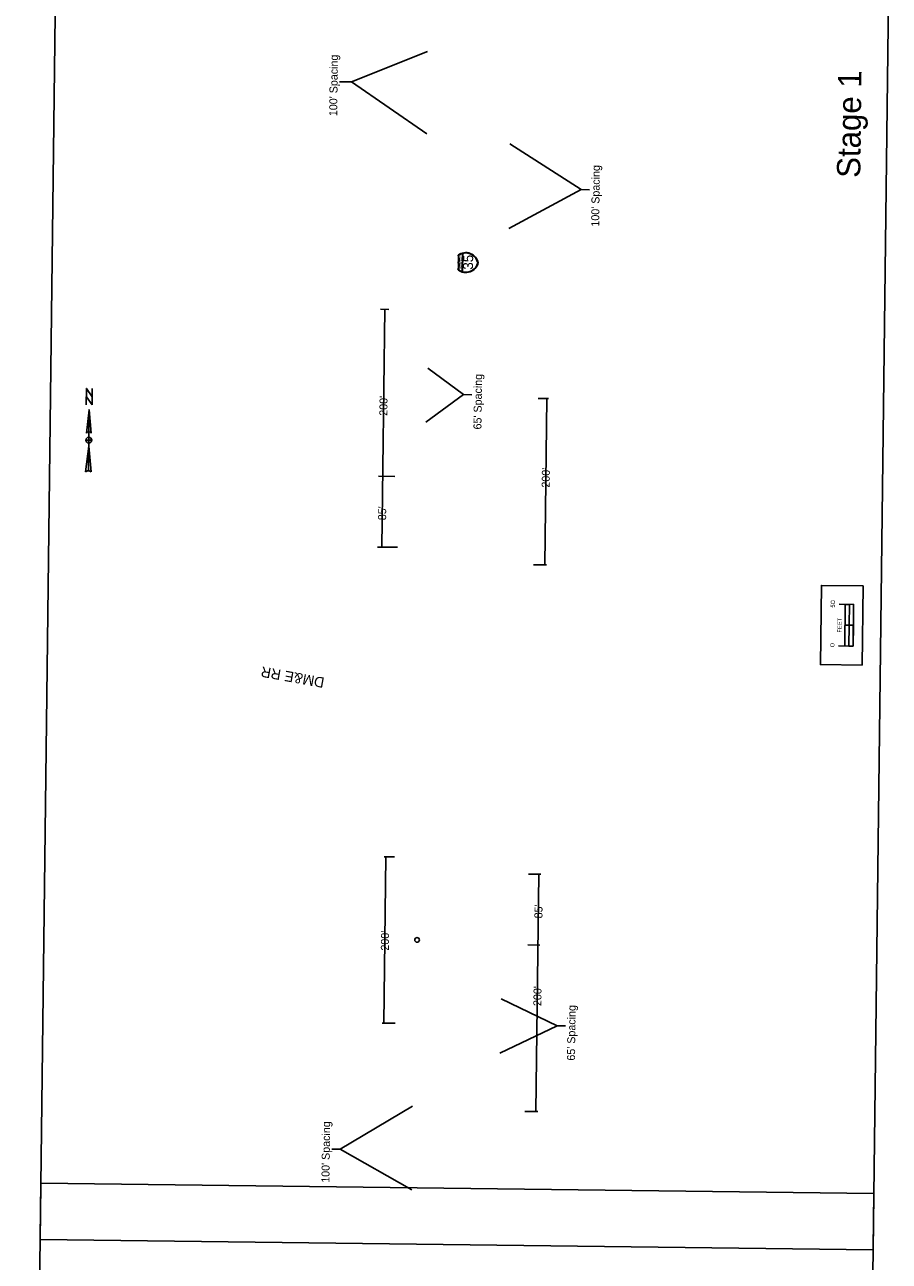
# Model space of a CAD drawing. Extents: x 4959127 to 4960275, y 3872379 to 3884458.
# Drawn here: x 4959182 to 4960220, y 3878365 to 3879849 of the extents above; entities that cross this region are included whole.
import ezdxf

# ---------------------------------------------------------------- set-up
doc = ezdxf.new("R2010")
doc.units = 0
for name, color, linetype in [('Cell', 7, 'Continuous'), ('dsnCellElements', 7, 'Continuous'), ('dsnCellsHighwaySymbols', 7, 'Continuous'), ('dsnCellsScaleBlock', 7, 'Continuous'), ('NamedBoundary', 7, 'Continuous'), ('SheetText', 7, 'Continuous'), ('Text', 7, 'Continuous')]:
    doc.layers.add(name, color=color, linetype=linetype)

msp = doc.modelspace()

# ---------------------------------------------------------------- linework, layer by layer
at = {"layer": 'Cell'}
for p, q in [((4959259.3, 3879386.7), (4959258.4, 3879313.4)), ((4959259.3, 3879386.7), (4959261.8, 3879358.5)), ((4959256.1, 3879358.5), (4959256.1, 3879358.5)), ((4959256.3, 3879358.8), (4959256.8, 3879359.4)), ((4959254.9, 3879312.1), (4959258.8, 3879343)), ((4959258.8, 3879346.5), (4959258.8, 3879346.5))]:
    msp.add_line(p, q, dxfattribs=at)
for points in [[(4959255.9, 3879392.4), (4959256.1, 3879412.1), (4959263, 3879402.1), (4959263.1, 3879412)], [(4959256.1, 3879358.5), (4959259.3, 3879386.7), (4959259, 3879359.9)], [(4959262.4, 3879350), (4959258.9, 3879350.1), (4959258.9, 3879353.6)], [(4959258.8, 3879346.5), (4959258.9, 3879350.1), (4959255.3, 3879350.1)], [(4959258.4, 3879313.4), (4959258.8, 3879343), (4959261.9, 3879312)]]:
    msp.add_lwpolyline(points, dxfattribs=at)
msp.add_lwpolyline([(4959262.9, 3879392.3), (4959256, 3879402.2), (4959256.1, 3879412.1), (4959263, 3879402.1)], close=True, dxfattribs=at)
for centre, radius, start, end in [((4959258.9, 3879350.1), 3.52, 89.2975, 179.2975), ((4959258.9, 3879356.4), 3.52, 89.3179, 142.4233), ((4959258.9, 3879350.1), 3.52, 359.2975, 89.2975), ((4959258.9, 3879356.4), 3.52, 36.1456, 89.3194), ((4959258.9, 3879350.1), 3.52, 179.2975, 269.2975), ((4959258.9, 3879350.1), 3.52, 269.2975, 359.2975), ((4959258.3, 3879308.3), 5.1, 89.2869, 132.9165), ((4959258.3, 3879308.3), 5.11, 45.6996, 89.2982)]:
    msp.add_arc(centre, radius, start, end, dxfattribs=at)
at = {"layer": 'dsnCellElements'}
msp.add_lwpolyline([(4960136.9, 3879080.9), (4960138.1, 3879175.9), (4960188.1, 3879175.3), (4960186.9, 3879080.3)], close=True, dxfattribs=at)
msp.add_lwpolyline([(4960136.9, 3879080.9), (4960138.1, 3879175.9), (4960188.1, 3879175.3), (4960186.9, 3879080.3)], close=True, dxfattribs=at)
msp.add_circle((4959652.9, 3878750.5), 2.75, dxfattribs=at)
at = {"layer": 'dsnCellsHighwaySymbols'}
for p, q in [((4959707.3, 3879574.1), (4959707, 3879552.4)), ((4959707.5, 3879552.3), (4959707.8, 3879574.3))]:
    msp.add_line(p, q, dxfattribs=at)
for centre, radius, start, end in [((4959711.4, 3879560.2), 15, 10.8347, 127.6287), ((4959711.4, 3879560.2), 14.5, 106.5608, 126.3017), ((4959711.4, 3879560.2), 14.5, 11.2271, 104.5442), ((4959687.7, 3879559.1), 15, 342.3065, 16.2887), ((4959711.5, 3879566.2), 15, 230.9665, 347.7605), ((4959687.8, 3879567.9), 15, 342.3065, 16.2887), ((4959687.8, 3879567.9), 15.5, 342.7231, 14.8585), ((4959687.7, 3879559.1), 15.5, 343.7366, 15.8721), ((4959711.5, 3879566.2), 14.5, 254.051, 347.368), ((4959711.5, 3879566.2), 14.5, 232.2935, 252.0342)]:
    msp.add_arc(centre, radius, start, end, dxfattribs=at)
at = {"layer": 'dsnCellsScaleBlock'}
msp.add_line((4960176.5, 3879128), (4960166.5, 3879128.1), dxfattribs=at)
msp.add_line((4960176.5, 3879128), (4960166.5, 3879128.1), dxfattribs=at)
for points in [[(4960186.9, 3879080.3), (4960136.9, 3879080.9), (4960138.1, 3879175.9), (4960188.1, 3879175.3)], [(4960171.5, 3879128), (4960171.8, 3879153), (4960166.8, 3879153.1), (4960166.5, 3879128.1)], [(4960176.2, 3879103), (4960176.5, 3879128), (4960171.5, 3879128), (4960171.2, 3879103)]]:
    msp.add_lwpolyline(points, close=True, dxfattribs=at)
for points in [[(4960158.7, 3879103.2), (4960176.2, 3879103), (4960176.8, 3879153), (4960159.3, 3879153.2)], [(4960166.2, 3879103.1), (4960166.8, 3879153.1)]]:
    msp.add_lwpolyline(points, dxfattribs=at)
at = {"layer": 'NamedBoundary'}
for points in [[(4959200.4, 3878391), (4960200.4, 3878378.7), (4960219.6, 3879946.1), (4959219.6, 3879958.4)], [(4959182, 3876891.1), (4960182, 3876878.8), (4960201.2, 3878446.2), (4959201.3, 3878458.5)]]:
    msp.add_lwpolyline(points, close=True, dxfattribs=at)
at = {"layer": 'SheetText'}
for p, q in [((4959574.3, 3879780), (4959665.3, 3879816.4)), ((4959849.9, 3879650.7), (4959764.3, 3879705.5)), ((4959618.9, 3879507), (4959609, 3879507.1)), ((4959610.7, 3879221.9), (4959614.2, 3879507.1)), ((4959798.2, 3879400.2), (4959810.8, 3879400)), ((4959806.1, 3879200.4), (4959808.5, 3879400.1)), ((4959626.2, 3879306.6), (4959606.6, 3879306.9)), ((4959629.5, 3879221.6), (4959605.5, 3879221.9)), ((4959792.6, 3879200.6), (4959808.4, 3879200.4)), ((4959613.2, 3878650.6), (4959615.6, 3878850.2)), ((4959626, 3878850.1), (4959613.3, 3878850.3)), ((4959786.7, 3878829.4), (4959801.4, 3878829.2)), ((4959795.6, 3878544.6), (4959799.1, 3878829.2)), ((4959786, 3878744.4), (4959800.4, 3878744.2)), ((4959626.7, 3878650.4), (4959610.9, 3878650.6)), ((4959560.6, 3878499.5), (4959647.3, 3878551.2)), ((4959782.1, 3878544.8), (4959797.9, 3878544.6))]:
    msp.add_line(p, q, dxfattribs=at)
for points in [[(4959559.7, 3879780.2), (4959574.3, 3879780), (4959664.8, 3879717.6)], [(4959860, 3879650.6), (4959849.9, 3879650.7), (4959762.9, 3879604.1)], [(4959708.5, 3879404.7), (4959708.5, 3879404.7), (4959665.7, 3879436.6)], [(4959718.6, 3879404.5), (4959708.5, 3879404.7), (4959663.6, 3879371.6)], [(4959820.9, 3878647.3), (4959820.9, 3878647.3), (4959753.8, 3878679.6)], [(4959830.9, 3878647.2), (4959820.9, 3878647.3), (4959752.2, 3878614.6)], [(4959550.6, 3878499.6), (4959560.6, 3878499.5), (4959646.5, 3878450.8)]]:
    msp.add_lwpolyline(points, dxfattribs=at)

# ---------------------------------------------------------------- texts
at = {"layer": 'dsnCellsHighwaySymbols'}
for s, height, p in [('T', 2.5, (4959706.6, 3879565.1)), ('S', 2.5, (4959706.6, 3879563.3)), ('R', 2.5, (4959706.6, 3879561.5)), ('E', 2.5, (4959706.6, 3879559.8)), ('T', 2.5, (4959706.6, 3879558.2)), ('E', 2.5, (4959706.7, 3879569.8)), ('T', 2.5, (4959706.7, 3879568.2)), ('A', 2.5, (4959706.7, 3879566.5)), ('35', 12, (4959720, 3879554.6)), ('N', 2.5, (4959706.5, 3879556.4)), ('I', 2.5, (4959706.5, 3879555.5))]:
    msp.add_text(s, height=height, rotation=89.2975, dxfattribs=at).set_placement(p)
at = {"layer": 'dsnCellsScaleBlock'}
for s, p in [('5O', (4960154.3, 3879149.2)), ('FEET', (4960162.4, 3879119.2)), ('O', (4960153.7, 3879101.6))]:
    msp.add_text(s, height=5, rotation=89.2975, dxfattribs=at).set_placement(p)
at = {"layer": 'SheetText'}
for s, height, rotation, p in [("100' Spacing", 9.6, 89.3042, (4959557, 3879738.8)), ("100' Spacing", 9.6, 89.3042, (4959871.4, 3879606.3)), ("65' Spacing", 9.6, 89.3042, (4959730.1, 3879362.9)), ("200'", 9.6, 89.2975, (4959617.2, 3879379.3)), ("200'", 9.6, 89.2975, (4959812, 3879293.1)), ("85'", 9.6, 89.2975, (4959615.7, 3879254)), ('DM&E RR', 12.48, 169.7212, (4959542.4, 3879065)), ("85'", 9.6, 89.2975, (4959803.3, 3878776.3)), ("200'", 9.6, 89.2975, (4959619, 3878737.6)), ("200'", 9.6, 89.2975, (4959802, 3878671.1)), ("65' Spacing", 9.6, 89.3042, (4959842.4, 3878605.6)), ("100' Spacing", 9.6, 89.2908, (4959547.7, 3878459))]:
    msp.add_text(s, height=height, rotation=rotation, dxfattribs=at).set_placement(p)
at = {"layer": 'Text'}
msp.add_text('Stage 1', height=28, rotation=89.2975, dxfattribs=at).set_placement((4960184.7, 3879664.7))

doc.saveas('drawing.dxf')
